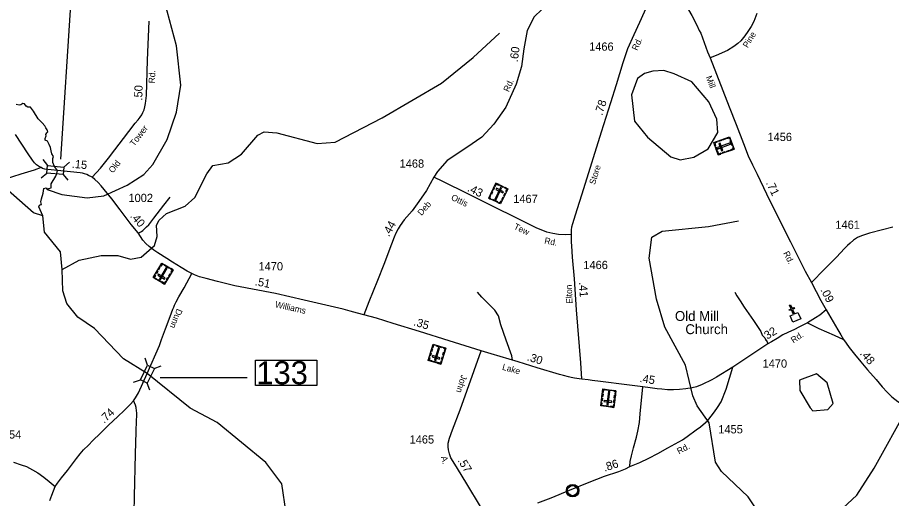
# Model space of a CAD drawing. Extents: x 2093524 to 2270757, y 289120 to 570408.
# Drawn here: x 2136094 to 2149355, y 503417 to 510705 of the extents above; entities that cross this region are included whole.
import ezdxf

# ---------------------------------------------------------------- set-up
doc = ezdxf.new("R2010")
doc.units = 0
for name, color, linetype in [('Exist Civil Demographics Community CELL', 7, 'Continuous'), ('Exist Cultural Cemetery CELL', 7, 'Continuous'), ('Exist Cultural Church CELL', 7, 'Continuous'), ('Exist Cultural Church Label', 7, 'Continuous'), ('Exist Hydrographic Creek Single Shore', 7, 'Continuous'), ('Exist Hydrographic Misc Water Feature', 7, 'Continuous'), ('Exist Hydrographic Pond Under 1500 Sq Ft', 7, 'Continuous'), ('Exist Road Non-System Type 51', 7, 'Continuous'), ('Exist Road Secondary Mileage Hundredths English Label', 7, 'Continuous'), ('Exist Road Secondary Structure Standard Bridge CELL', 7, 'Continuous'), ('Exist Road Secondary Structure Standard Bridge Number Label', 7, 'Continuous'), ('Exist Road Secondary Type 51 Attributed', 7, 'Continuous'), ('Exist Road Secondary Type 51 Label', 7, 'Continuous'), ('Exist Road Secondary Type 51 Number Label', 7, 'Continuous')]:
    doc.layers.add(name, color=color, linetype=linetype)

msp = doc.modelspace()

# ---------------------------------------------------------------- linework, layer by layer
at = {"layer": 'Exist Civil Demographics Community CELL'}
msp.add_lwpolyline([(2144440, 503548), (2144441, 503554), (2144442, 503561), (2144445, 503568), (2144448, 503574), (2144452, 503579), (2144455, 503584), (2144459, 503589), (2144464, 503593), (2144469, 503598), (2144475, 503602), (2144480, 503605), (2144485, 503607), (2144490, 503609), (2144496, 503611), (2144500, 503612), (2144505, 503613), (2144509, 503614), (2144516, 503614), (2144520, 503614), (2144526, 503614), (2144531, 503613), (2144535, 503612), (2144541, 503610), (2144546, 503609), (2144552, 503606), (2144559, 503602), (2144564, 503599), (2144569, 503595), (2144572, 503591), (2144576, 503587), (2144580, 503582), (2144583, 503578), (2144586, 503573), (2144589, 503568), (2144591, 503563), (2144592, 503558), (2144594, 503553), (2144595, 503547), (2144595, 503542), (2144596, 503536), (2144595, 503530), (2144595, 503525), (2144594, 503519), (2144592, 503513), (2144590, 503507), (2144588, 503502), (2144585, 503496), (2144582, 503491), (2144578, 503486), (2144574, 503481), (2144569, 503476), (2144564, 503472), (2144559, 503469), (2144554, 503466), (2144548, 503463), (2144540, 503460), (2144534, 503459), (2144528, 503458), (2144523, 503457), (2144519, 503457), (2144513, 503457), (2144509, 503457), (2144503, 503458), (2144498, 503459), (2144493, 503461), (2144488, 503463), (2144483, 503465), (2144479, 503467), (2144472, 503471), (2144467, 503475), (2144462, 503480), (2144457, 503485), (2144454, 503488), (2144451, 503493), (2144447, 503500), (2144446, 503503), (2144444, 503507), (2144441, 503516), (2144440, 503523), (2144439, 503528), (2144439, 503534), (2144439, 503539), (2144439, 503545)], close=True, dxfattribs=at)
for radius in [94.3, 76.7]:
    msp.add_circle((2144517, 503536), radius, dxfattribs=at)
at = {"layer": 'Exist Cultural Cemetery CELL'}
for points in [[(2146726, 508623), (2146658, 508810), (2146898, 508897), (2146966, 508709)], [(2146699, 508824), (2146703, 508814), (2146673, 508803), (2146686, 508765), (2146676, 508761), (2146658, 508810)], [(2146772, 508839), (2146731, 508824), (2146727, 508835), (2146768, 508849)], [(2146833, 508861), (2146793, 508846), (2146789, 508857), (2146830, 508872)], [(2146909, 508865), (2146898, 508862), (2146891, 508882), (2146853, 508868), (2146849, 508879), (2146898, 508897)], [(2146935, 508760), (2146906, 508839), (2146917, 508843), (2146946, 508763)], [(2146701, 508692), (2146683, 508741), (2146694, 508745), (2146712, 508696)], [(2146717, 508735), (2146723, 508717), (2146913, 508787), (2146907, 508804)], [(2146776, 508684), (2146794, 508690), (2146754, 508801), (2146736, 508795)], [(2146900, 508686), (2146859, 508671), (2146855, 508681), (2146896, 508696)], [(2146954, 508741), (2146943, 508737), (2146951, 508716), (2146913, 508702), (2146917, 508692), (2146966, 508709)], [(2146767, 508637), (2146763, 508648), (2146733, 508637), (2146719, 508675), (2146709, 508671), (2146726, 508623)], [(2146837, 508663), (2146796, 508648), (2146792, 508659), (2146833, 508673)], [(2143353, 508196), (2143533, 508109), (2143423, 507880), (2143243, 507966)], [(2143335, 508157), (2143345, 508152), (2143359, 508181), (2143395, 508163), (2143400, 508173), (2143353, 508196)], [(2143420, 508164), (2143467, 508141), (2143462, 508131), (2143415, 508153)], [(2143273, 508029), (2143292, 508068), (2143302, 508063), (2143284, 508024)], [(2143303, 508090), (2143321, 508129), (2143332, 508124), (2143313, 508085)], [(2143439, 508122), (2143422, 508130), (2143334, 507947), (2143351, 507939)], [(2143361, 508117), (2143353, 508100), (2143459, 508049), (2143467, 508066)], [(2143472, 508009), (2143491, 508048), (2143501, 508043), (2143482, 508004)], [(2143514, 508070), (2143504, 508075), (2143518, 508104), (2143481, 508122), (2143486, 508132), (2143533, 508109)], [(2143273, 507952), (2143278, 507962), (2143258, 507972), (2143276, 508008), (2143266, 508013), (2143243, 507966)], [(2143300, 507952), (2143376, 507915), (2143371, 507905), (2143295, 507941)], [(2143393, 507894), (2143398, 507905), (2143417, 507895), (2143435, 507932), (2143445, 507927), (2143423, 507880)], [(2143444, 507950), (2143462, 507989), (2143473, 507984), (2143454, 507945)], [(2138327, 506663), (2138155, 506763), (2138283, 506983), (2138455, 506883)], [(2138311, 506967), (2138306, 506957), (2138287, 506968), (2138266, 506933), (2138257, 506939), (2138283, 506983)], [(2138223, 506858), (2138201, 506821), (2138191, 506827), (2138213, 506864)], [(2138256, 506915), (2138234, 506878), (2138225, 506883), (2138246, 506921)], [(2138247, 506743), (2138263, 506734), (2138365, 506909), (2138349, 506919)], [(2138399, 506902), (2138326, 506945), (2138332, 506955), (2138405, 506912)], [(2138426, 506900), (2138420, 506890), (2138439, 506879), (2138419, 506844), (2138429, 506838), (2138455, 506883)], [(2138176, 506801), (2138186, 506795), (2138170, 506767), (2138205, 506747), (2138199, 506737), (2138155, 506763)], [(2138263, 506700), (2138218, 506726), (2138224, 506736), (2138268, 506710)], [(2138326, 506742), (2138335, 506759), (2138233, 506818), (2138224, 506802)], [(2138348, 506701), (2138339, 506706), (2138322, 506678), (2138287, 506699), (2138282, 506689), (2138327, 506663)], [(2138386, 506765), (2138364, 506727), (2138354, 506733), (2138376, 506770)], [(2138420, 506823), (2138398, 506785), (2138388, 506791), (2138410, 506828)], [(2142517, 505452), (2142327, 505510), (2142401, 505754), (2142592, 505696)], [(2142391, 505682), (2142378, 505640), (2142367, 505643), (2142380, 505685)], [(2142433, 505744), (2142429, 505733), (2142408, 505740), (2142397, 505701), (2142386, 505704), (2142401, 505754)], [(2142422, 505512), (2142439, 505507), (2142499, 505701), (2142481, 505706)], [(2142533, 505702), (2142452, 505726), (2142455, 505737), (2142537, 505713)], [(2142560, 505706), (2142557, 505695), (2142578, 505688), (2142566, 505649), (2142576, 505646), (2142592, 505696)], [(2142339, 505552), (2142350, 505549), (2142341, 505518), (2142380, 505506), (2142376, 505495), (2142327, 505511)], [(2142372, 505619), (2142359, 505577), (2142348, 505580), (2142361, 505622)], [(2142498, 505529), (2142504, 505547), (2142391, 505582), (2142385, 505564)], [(2142552, 505565), (2142539, 505523), (2142528, 505527), (2142541, 505568)], [(2142571, 505629), (2142559, 505588), (2142548, 505591), (2142560, 505632)], [(2142446, 505474), (2142397, 505489), (2142400, 505500), (2142450, 505485)], [(2142530, 505494), (2142519, 505497), (2142510, 505466), (2142471, 505478), (2142468, 505468), (2142517, 505452)], [(2145140, 504797), (2144943, 504823), (2144977, 505076), (2145174, 505050)], [(2144978, 505003), (2144973, 504960), (2144961, 504961), (2144967, 505004)], [(2145009, 505072), (2145008, 505060), (2144986, 505063), (2144981, 505023), (2144970, 505024), (2144977, 505076)], [(2145115, 505046), (2145031, 505057), (2145033, 505068), (2145117, 505057)], [(2145036, 504841), (2145055, 504838), (2145081, 505039), (2145063, 505042)], [(2145141, 505054), (2145140, 505043), (2145161, 505040), (2145156, 505000), (2145167, 504998), (2145174, 505050)], [(2145165, 504980), (2145159, 504937), (2145148, 504939), (2145153, 504982)], [(2144949, 504866), (2144960, 504865), (2144956, 504833), (2144996, 504828), (2144994, 504817), (2144943, 504824)], [(2144970, 504937), (2144964, 504894), (2144953, 504896), (2144958, 504939)], [(2145109, 504870), (2145111, 504889), (2144995, 504904), (2144992, 504886)], [(2145146, 504840), (2145135, 504842), (2145131, 504810), (2145090, 504815), (2145089, 504804), (2145140, 504797)], [(2145156, 504914), (2145150, 504871), (2145139, 504872), (2145145, 504915)], [(2145067, 504807), (2145016, 504814), (2145017, 504825), (2145068, 504818)]]:
    msp.add_lwpolyline(points, close=True, dxfattribs=at)
at = {"layer": 'Exist Cultural Church CELL'}
msp.add_lwpolyline([(2147817, 506184), (2147869, 506207), (2147838, 506277), (2147809, 506264), (2147802, 506278), (2147831, 506291), (2147807, 506346), (2147822, 506353), (2147846, 506298), (2147875, 506311), (2147882, 506296), (2147853, 506283), (2147883, 506214), (2147936, 506237), (2147979, 506140), (2147860, 506087)], close=True, dxfattribs=at)
at = {"layer": 'Exist Hydrographic Creek Single Shore'}
msp.add_line((2136478, 507702), (2136418, 507838), dxfattribs=at)
for points in [[(2136546, 508097), (2136769, 508021), (2137152, 507971), (2137403, 508005), (2137760, 508166), (2138009, 508325), (2138150, 508476), (2138365, 508859), (2138505, 509269), (2138570, 509678), (2138508, 510276), (2138330, 510933)], [(2136656, 508450), (2136633, 508510), (2136630, 508570), (2136643, 508600), (2136617, 508642), (2136604, 508687), (2136595, 508737), (2136577, 508779), (2136549, 508829), (2136514, 508847), (2136514, 508870), (2136531, 508912), (2136522, 508935), (2136541, 508957), (2136554, 508972), (2136549, 508990), (2136546, 509003), (2136526, 509035), (2136507, 509066), (2136467, 509111), (2136408, 509172), (2136335, 509287), (2136290, 509345), (2136250, 509348), (2136227, 509360), (2136202, 509396), (2136176, 509403), (2136147, 509381), (2136121, 509378), (2136076, 509385)], [(2136478, 507702), (2136338, 507745), (2135910, 508117), (2135827, 508224), (2135416, 508564), (2135299, 508628), (2134810, 508379), (2134502, 508342), (2134234, 508384), (2134034, 508499), (2133758, 508813), (2133657, 509016)], [(2136701, 508387), (2136656, 508450)], [(2136418, 507838), (2136431, 507871), (2136447, 507866), (2136457, 507874), (2136449, 507911), (2136457, 507956), (2136486, 508044), (2136496, 508115), (2136531, 508125), (2136546, 508097), (2136572, 508112), (2136605, 508122), (2136604, 508185), (2136674, 508301), (2136690, 508339), (2136701, 508387)], [(2136774, 506886), (2136747, 507152), (2136505, 507453), (2136478, 507702)], [(2138063, 505310), (2137705, 505532), (2137262, 505991), (2137011, 506163), (2136843, 506370), (2136784, 506561), (2136774, 506886)], [(2141284, 500701), (2140254, 501686), (2140162, 501894), (2140094, 502145), (2140075, 502693), (2140173, 503193), (2140104, 503637), (2139861, 503961), (2139126, 504566), (2138716, 504787), (2138063, 505310)], [(2147690, 502435), (2147782, 502470), (2148338, 503013), (2148827, 503466), (2149092, 503877), (2149603, 504798)]]:
    msp.add_lwpolyline(points, dxfattribs=at)
at = {"layer": 'Exist Hydrographic Misc Water Feature'}
for points in [[(2136774, 506886), (2137031, 507029), (2137364, 507097), (2137615, 507099), (2137807, 507043), (2137973, 507075), (2138172, 507252), (2138213, 507386), (2138204, 507560), (2138246, 507634), (2138353, 507734), (2138636, 507846), (2138785, 507978), (2138967, 508338), (2139058, 508464), (2139291, 508505), (2139491, 508633), (2139739, 508923), (2139839, 508973), (2140031, 508960), (2140640, 508797), (2140914, 508814), (2141629, 509183), (2142527, 509710), (2143008, 510097), (2143406, 510466)], [(2147631, 502551), (2147589, 502703), (2147362, 503167), (2147178, 503443), (2146776, 503825), (2146684, 503965), (2146590, 504564), (2146405, 504823), (2146338, 504972), (2146228, 505437), (2145917, 506011), (2145790, 506436), (2145679, 507059), (2145719, 507376), (2145877, 507468), (2146577, 507539), (2147034, 507625)]]:
    msp.add_lwpolyline(points, dxfattribs=at)
at = {"layer": 'Exist Hydrographic Pond Under 1500 Sq Ft'}
for points in [[(2146147, 508551), (2146355, 508587), (2146571, 508714), (2146720, 508963), (2146703, 509164), (2146585, 509428), (2146325, 509729), (2146058, 509852), (2145900, 509901), (2145733, 509892), (2145608, 509858), (2145500, 509781), (2145410, 509534), (2145453, 509133), (2145654, 508893), (2146005, 508594), (2146147, 508551)], [(2148163, 504745), (2148388, 504764), (2148471, 504857), (2148378, 505171), (2148219, 505305), (2147961, 505212), (2147962, 505054), (2148121, 504789), (2148163, 504745)]]:
    msp.add_lwpolyline(points, dxfattribs=at)
at = {"layer": 'Exist Road Non-System Type 51'}
for points in [[(2137927, 507442), (2137943, 507446), (2137957, 507452), (2137975, 507463), (2137995, 507479), (2138054, 507534), (2138085, 507565), (2138161, 507664), (2138317, 507861), (2138411, 507983)], [(2143602, 505513), (2143596, 505578), (2143507, 505817), (2143429, 506050), (2143390, 506183), (2143335, 506272), (2143246, 506361), (2143140, 506467), (2143074, 506545)], [(2146978, 506543), (2147006, 506488), (2147057, 506411), (2147121, 506316), (2147189, 506216), (2147261, 506115), (2147302, 506054), (2147331, 506010), (2147372, 505945), (2147392, 505894), (2147434, 505849), (2147443, 505825), (2147466, 505791), (2147476, 505759)], [(2148082, 506078), (2148250, 505991), (2148484, 505892), (2148627, 505827)], [(2145385, 503903), (2145392, 503977), (2145410, 504062), (2145440, 504184), (2145484, 504347), (2145507, 504436), (2145530, 504566), (2145543, 504700), (2145583, 505111)], [(2136792, 502654), (2136877, 502684), (2137113, 502791), (2137615, 503007), (2137739, 503063), (2137825, 503107), (2137842, 503119), (2137852, 503130), (2137860, 503144), (2137864, 503156), (2137865, 503202), (2137872, 503448), (2137887, 504092), (2137894, 504427), (2137899, 504597), (2137905, 504671), (2137904, 504713), (2137900, 504743), (2137893, 504795), (2137884, 504832), (2137852, 504902)]]:
    msp.add_lwpolyline(points, dxfattribs=at)
at = {"layer": 'Exist Road Secondary Structure Standard Bridge CELL'}
for p, q in [((2136479, 508552), (2136550, 508464)), ((2136797, 508439), (2136884, 508511)), ((2136451, 508277), (2136539, 508349)), ((2136786, 508327), (2136858, 508239)), ((2138067, 505437), (2138030, 505544)), ((2138169, 505388), (2138276, 505425)), ((2137852, 505177), (2137959, 505214)), ((2138100, 505057), (2138063, 505164))]:
    msp.add_line(p, q, dxfattribs=at)
for points in [[(2136550, 508464), (2136797, 508440), (2136786, 508325), (2136539, 508349)], [(2137959, 505214), (2138066, 505438), (2138171, 505387), (2138063, 505164)]]:
    msp.add_lwpolyline(points, close=True, dxfattribs=at)
at = {"layer": 'Exist Road Secondary Structure Standard Bridge Number Label'}
for p, q in [((2136753, 508561), (2136911, 510979)), ((2138257, 505248), (2139581, 505248))]:
    msp.add_line(p, q, dxfattribs=at)
msp.add_lwpolyline([(2139706, 505512), (2140635, 505512), (2140635, 505128), (2139706, 505128)], close=True, dxfattribs=at)
at = {"layer": 'Exist Road Secondary Type 51 Attributed'}
for points in [[(2145915, 511438), (2146324, 510735), (2146399, 510588), (2146439, 510511), (2146461, 510470), (2146561, 510186), (2146603, 510096)], [(2144499, 507417), (2144498, 507444), (2144501, 507485), (2144507, 507531), (2144520, 507586), (2144561, 507713), (2144685, 508114), (2144955, 508975), (2145096, 509416), (2145183, 509690), (2145286, 510024), (2145329, 510159), (2145355, 510235), (2145450, 510448), (2145534, 510635), (2145839, 511314)], [(2144050, 510827), (2143934, 510714), (2143829, 510509), (2143774, 510233), (2143739, 509963), (2143658, 509697), (2143503, 509346), (2143323, 509091), (2143138, 508891), (2142912, 508735), (2142612, 508540), (2142467, 508370), (2142413, 508288)], [(2147310, 510765), (2147268, 510644), (2147225, 510567), (2147177, 510492), (2147130, 510429), (2147070, 510354), (2147025, 510311), (2146962, 510264), (2146865, 510206), (2146696, 510130), (2146603, 510096)], [(2137228, 508286), (2137352, 508420), (2137473, 508573), (2137570, 508699), (2137705, 508871), (2137786, 508979), (2137882, 509105), (2137923, 509154), (2137954, 509196), (2137981, 509229), (2137997, 509265), (2138014, 509304), (2138027, 509352), (2138038, 509404), (2138052, 509526), (2138069, 510061), (2138092, 510651)], [(2146603, 510096), (2146892, 509352), (2146997, 509082), (2147107, 508796), (2147179, 508608), (2147248, 508475), (2147315, 508330), (2147458, 508033), (2147605, 507734), (2147823, 507305), (2148043, 506861), (2148140, 506688)], [(2136451, 508430), (2136411, 508451), (2136385, 508471), (2136352, 508504), (2136321, 508545), (2136255, 508638), (2136065, 508930)], [(2136451, 508430), (2136348, 508394), (2136145, 508330), (2135893, 508251), (2135551, 508146), (2135366, 508088), (2135235, 508054), (2135039, 508020), (2134676, 507972), (2133849, 507862), (2132663, 507756)], [(2136701, 508387), (2136508, 508409), (2136474, 508418), (2136451, 508430)], [(2137228, 508286), (2137174, 508311), (2137146, 508324), (2137111, 508337), (2137081, 508345), (2137043, 508354), (2136701, 508387)], [(2138740, 506824), (2138667, 506864), (2138576, 506919), (2138448, 507000), (2138359, 507052), (2138222, 507139), (2138163, 507180), (2138130, 507206), (2138094, 507233), (2138039, 507282), (2137998, 507333), (2137927, 507442), (2137821, 507567), (2137654, 507790), (2137525, 507958), (2137363, 508156), (2137320, 508203), (2137269, 508250), (2137228, 508286)], [(2142413, 508288), (2142301, 508086), (2142221, 507970), (2142159, 507881), (2142081, 507777), (2141960, 507637), (2141902, 507552), (2141871, 507501), (2141836, 507438), (2141809, 507376), (2141769, 507273), (2141651, 506962), (2141554, 506722), (2141427, 506396), (2141348, 506200)], [(2144499, 507417), (2144403, 507414), (2144302, 507417), (2144217, 507430), (2144125, 507453), (2144063, 507476), (2143972, 507515), (2143861, 507570), (2143681, 507658), (2143300, 507846), (2142926, 508034), (2142550, 508219), (2142413, 508288)], [(2149376, 507529), (2149218, 507489), (2149019, 507435), (2148900, 507398), (2148841, 507370), (2148779, 507330), (2148729, 507286), (2148686, 507248), (2148644, 507206), (2148518, 507073), (2148419, 506973), (2148337, 506892), (2148140, 506688)], [(2144655, 505227), (2144640, 505474), (2144578, 506277), (2144544, 506743), (2144516, 507075), (2144503, 507247), (2144501, 507300), (2144498, 507352), (2144499, 507417)], [(2138063, 505310), (2138248, 505736), (2138278, 505824), (2138339, 505988), (2138411, 506173), (2138453, 506286), (2138464, 506318), (2138476, 506346), (2138485, 506367), (2138502, 506397), (2138543, 506472), (2138622, 506609), (2138740, 506824)], [(2141348, 506200), (2141254, 506224), (2141143, 506256), (2141036, 506284), (2140770, 506347), (2140442, 506421), (2140009, 506525), (2139392, 506641), (2139128, 506704), (2138955, 506748), (2138855, 506774), (2138780, 506805), (2138740, 506824)], [(2148140, 506688), (2148285, 506418), (2148362, 506275)], [(2143130, 505656), (2142646, 505806), (2142191, 505947), (2141792, 506066), (2141539, 506148), (2141348, 506200)], [(2148362, 506275), (2148268, 506195), (2148204, 506152), (2148159, 506127), (2148082, 506078), (2147947, 506011), (2147882, 505978), (2147783, 505934), (2147704, 505896), (2147619, 505842), (2147536, 505789), (2147476, 505759), (2146945, 505409)], [(2148362, 506275), (2148540, 505973), (2148588, 505896), (2148627, 505827), (2148666, 505771), (2148713, 505704), (2148793, 505604), (2148888, 505490), (2148990, 505368), (2149121, 505220), (2149213, 505110), (2149287, 505026), (2149362, 504959), (2149453, 504888), (2149515, 504847), (2149603, 504798)], [(2143351, 502914), (2143291, 503015), (2143117, 503293), (2142912, 503641), (2142770, 503869), (2142704, 503977), (2142670, 504035), (2142651, 504094), (2142634, 504154), (2142627, 504200), (2142630, 504254), (2142648, 504332), (2142692, 504459), (2142808, 504761), (2143130, 505656)], [(2144655, 505227), (2144615, 505232), (2144544, 505242), (2144494, 505251), (2144456, 505259), (2144378, 505279), (2144319, 505298), (2143981, 505395), (2143691, 505487), (2143281, 505609), (2143130, 505656)], [(2143990, 503349), (2144191, 503429), (2144469, 503541), (2144768, 503665), (2145000, 503757), (2145219, 503828), (2145320, 503864), (2145385, 503903), (2145538, 503964), (2145671, 504027), (2145807, 504098), (2145962, 504185), (2146185, 504307), (2146256, 504357), (2146392, 504457), (2146459, 504505), (2146567, 504601), (2146618, 504662), (2146671, 504731), (2146714, 504794), (2146768, 504879), (2146848, 505073), (2146945, 505409)], [(2146945, 505409), (2146702, 505254), (2146631, 505216), (2146481, 505143), (2146397, 505110), (2146332, 505094), (2146234, 505076), (2146140, 505066), (2146048, 505061), (2145958, 505063), (2145872, 505071), (2145798, 505078), (2145693, 505093), (2145583, 505111), (2145220, 505152), (2145060, 505173), (2144941, 505188), (2144813, 505204), (2144751, 505214), (2144655, 505227)], [(2136667, 503598), (2136702, 503648), (2136762, 503732), (2136852, 503842), (2136992, 504022), (2137043, 504093), (2137098, 504152), (2137170, 504224), (2137239, 504295), (2137347, 504400), (2137476, 504526), (2137619, 504659), (2137712, 504751), (2137780, 504818), (2137806, 504843), (2137852, 504899), (2137885, 504942), (2137930, 505019), (2138063, 505310)], [(2136033, 503969), (2136148, 503929), (2136231, 503899), (2136321, 503851), (2136402, 503804), (2136496, 503738), (2136577, 503672), (2136667, 503598)], [(2136585, 503384), (2136613, 503465), (2136667, 503598)]]:
    msp.add_lwpolyline(points, dxfattribs=at)

# ---------------------------------------------------------------- texts
at = {"layer": 'Exist Cultural Church Label'}
for s, p in [('Old Mill', (2146069, 506107)), ('Church', (2146227, 505907))]:
    msp.add_text(s, height=150, dxfattribs=at).set_placement(p)
at = {"layer": 'Exist Road Secondary Mileage Hundredths English Label'}
for s, rotation, p in [('.60', 82.6175, (2143684, 510025)), ('.50', 88.2033, (2137987, 509446)), ('.78', 72.2967, (2144965, 509213)), ('.15', 354.5572, (2136914, 508429)), ('.71', 295.5837, (2147447, 508200)), ('.43', 334.3217, (2142908, 508079)), ('.40', 310.3423, (2137796, 507692)), ('.44', 60.9225, (2141730, 507375)), ('.51', 349.3319, (2139689, 506649)), ('.41', 274.1159, (2144611, 506694)), ('.09', 297.1125, (2148273, 506578)), ('.35', 342.7711, (2142094, 506043)), ('.32', 32.1846, (2147431, 505797)), ('.30', 342.4407, (2143817, 505512)), ('.48', 309.7596, (2148869, 505611)), ('.45', 350.5705, (2145526, 505184)), ('.74', 43.0065, (2137408, 504548)), ('.57', 301.716, (2142768, 503992)), ('.86', 18.0741, (2145003, 503823))]:
    msp.add_text(s, height=125, rotation=rotation, dxfattribs=at).set_placement(p)
at = {"layer": 'Exist Road Secondary Structure Standard Bridge Number Label'}
msp.add_text('133', height=350, dxfattribs=at).set_placement((2139719, 505147))
at = {"layer": 'Exist Road Secondary Type 51 Label'}
for s, rotation, p in [('Pine', 58.7127, (2147173, 510237)), ('Rd.', 65.4836, (2145496, 510197)), ('Rd.', 87.274, (2138178, 509706)), ('Rd.', 66.1238, (2143548, 509570)), ('Mill', 291.1697, (2146535, 509802)), ('Tower', 52.5528, (2137865, 508746)), ('Old', 51.7714, (2137542, 508340)), ('Store', 72.6223, (2144856, 508165)), ('Deb', 49.1092, (2142225, 507695)), ('Ottis', 334.3217, (2142664, 507947)), ('Tew', 334.0461, (2143615, 507506)), ('Rd.', 348.6901, (2144082, 507282)), ('Rd.', 296.9116, (2147709, 507135)), ('Elton', 92.2477, (2144516, 506370)), ('Williams', 347.5815, (2139997, 506315)), ('Dunn', 248.3167, (2138514, 506300)), ('Rd.', 33.3376, (2147866, 505766)), ('Lake', 344.4418, (2143441, 505369)), ('John', 252.6086, (2142830, 505299)), ('Rd.', 28.6481, (2146131, 504084)), ('A.', 285.5455, (2142518, 504045))]:
    msp.add_text(s, height=95, rotation=rotation, dxfattribs=at).set_placement(p)
at = {"layer": 'Exist Road Secondary Type 51 Number Label'}
for s, p in [('1466', (2144767, 510202)), ('1456', (2147473, 508833)), ('1468', (2141892, 508429)), ('1002', (2137778, 507909)), ('1467', (2143616, 507894)), ('1461', (2148503, 507503)), ('1470', (2139751, 506873)), ('1466', (2144679, 506893)), ('1470', (2147399, 505399)), ('1454', (2135779, 504324)), ('1455', (2146727, 504403)), ('1465', (2142043, 504249))]:
    msp.add_text(s, height=125, dxfattribs=at).set_placement(p)

doc.saveas('drawing.dxf')
